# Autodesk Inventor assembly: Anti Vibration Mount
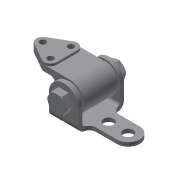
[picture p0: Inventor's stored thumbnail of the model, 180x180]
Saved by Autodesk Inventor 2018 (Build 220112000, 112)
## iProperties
Created: 2011-07
Part Number: Anti Vibration Mount
Document SubType Name: Assembly
Designer: CadCim
Author: CadCim
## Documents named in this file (5)
- E:\_Deepak\Inventor\Autodesk Inventor_2017_Project\Resources\Inventor_2018_tut\c09_Inv_tut_2018\c09_tut03_inv\Anti Vibration Mount\Anti Vibration Mount.iam
- E:\_Deepak\Inventor\Autodesk Inventor_2017_Project\Resources\Inventor_2018_tut\c09_Inv_tut_2018\c09_tut03_inv\Anti Vibration Mount\Yoke Plate.ipt
- E:\_Deepak\Inventor\Autodesk Inventor_2017_Project\Resources\Inventor_2018_tut\c09_Inv_tut_2018\c09_tut03_inv\Anti Vibration Mount\Body-Bushing Ruber.iam
- E:\_Deepak\Inventor\Autodesk Inventor_2017_Project\Resources\Inventor_2018_tut\c09_Inv_tut_2018\c09_tut03_inv\Anti Vibration Mount\Hex Bolt.ipt
- E:\_Deepak\Inventor\Autodesk Inventor_2017_Project\Resources\Inventor_2018_tut\c09_Inv_tut_2018\c09_tut03_inv\Anti Vibration Mount\Nut.ipt
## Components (4 placed, 4 different names)
1. Yoke Plate:1 — Insert:1, Angle:1, Mate:1, Mate:2, Mate:3
2. Body-Bushing Ruber:1 [sub-assembly] — Insert:1, Angle:1
3. Hex Bolt:1 — Mate:2, Mate:3, Mate:4
4. Nut:1 — Mate:1, Mate:4
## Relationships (6: Mate 4, Insert 1, Angle 1)
- Insert:1: Yoke Plate:1 ↔ Body-Bushing Ruber:1
- Angle:1: Yoke Plate:1 ↔ Body-Bushing Ruber:1
- Mate:1: Yoke Plate:1 ↔ Nut:1
- Mate:2: Yoke Plate:1 ↔ Hex Bolt:1
- Mate:3: Yoke Plate:1 ↔ Hex Bolt:1
- Mate:4: Hex Bolt:1 ↔ Nut:1
